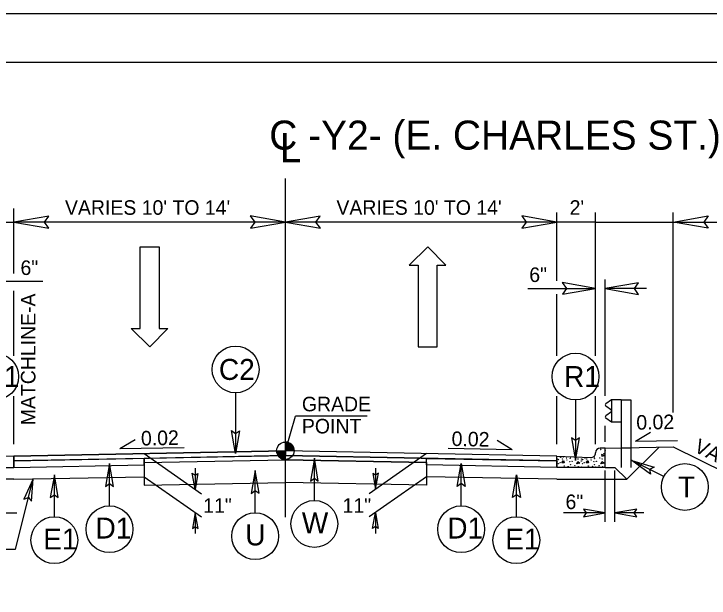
# Model space of a CAD drawing. Extents: x 1487909 to 1489267, y 497866 to 499814.
# Drawn here: x 1488985.22 to 1489021.07, y 498066.51 to 498096.65 of the extents above; entities that cross this region are included whole.
import ezdxf

# ---------------------------------------------------------------- set-up
doc = ezdxf.new("R2010")
doc.units = 0
for name, color, linetype in [('Exist XS Ground Line', 7, 'Continuous'), ('Old_Level_10', 7, 'Continuous'), ('Prop Dimension', 7, 'Continuous'), ('Prop Dimension Text', 7, 'Continuous'), ('Prop Lane Arrow CELL', 7, 'Continuous'), ('Prop Shade Light', 7, 'Continuous'), ('Prop Shade Medium', 7, 'Continuous'), ('Prop Terminator CELL', 7, 'Continuous'), ('Sheet Plot Border Outside CELL', 7, 'Continuous'), ('Sheet Typical CELL', 7, 'Continuous'), ('Typical Curb CELL', 7, 'Continuous'), ('Typical Detail Wedge2 CELL', 7, 'Continuous'), ('Typical Grade Point Symbol CELL', 7, 'Continuous'), ('Typical Guardrail CELL', 7, 'Continuous'), ('Typical Hinge Slope Arterial CELL', 7, 'Continuous'), ('Typical Hinge Slope Interstate CELL', 7, 'Continuous'), ('Typical ID Circle CELL', 7, 'Continuous'), ('Typical Pavement Slope CELL', 7, 'Continuous'), ('Typical Pavement Slope Information CELL', 7, 'Continuous'), ('Typical Terminator CELL', 7, 'Continuous'), ('Typical Text Grade Point CELL', 7, 'Continuous'), ('Typical Text ID Circle CELL', 7, 'Continuous')]:
    doc.layers.add(name, color=color, linetype=linetype)

msp = doc.modelspace()

# ---------------------------------------------------------------- linework, layer by layer
at = {"layer": 'Exist XS Ground Line'}
for p, q in [((1488991.931, 498073.498), (1488999.218, 498073.644)), ((1489006.506, 498073.498), (1488999.218, 498073.644)), ((1488991.931, 498073.498), (1488991.931, 498072.333)), ((1489006.506, 498073.498), (1489006.506, 498072.333)), ((1488991.931, 498072.333), (1488999.218, 498072.479)), ((1489006.506, 498072.333), (1488999.218, 498072.479))]:
    msp.add_line(p, q, dxfattribs=at)
at = {"layer": 'Old_Level_10'}
for p, q in [((1488991.931, 498073.718), (1488985.219, 498073.584)), ((1488985.219, 498073.584), (1488985.219, 498073.251)), ((1488991.931, 498073.385), (1488991.931, 498073.718)), ((1489006.506, 498073.385), (1489006.506, 498073.718)), ((1489006.506, 498073.718), (1489013.218, 498073.584)), ((1489013.218, 498073.584), (1489013.222, 498073.251)), ((1488985.219, 498073.251), (1488991.931, 498073.385)), ((1488991.931, 498073.385), (1488991.931, 498073.385)), ((1489013.222, 498073.251), (1489006.506, 498073.385)), ((1489006.506, 498073.385), (1489006.506, 498073.385))]:
    msp.add_line(p, q, dxfattribs=at)
at = {"layer": 'Prop Dimension'}
for p, q in [((1488999.218, 498070.68), (1488999.218, 498088.153)), ((1488985.219, 498083.267), (1488985.219, 498086.616)), ((1489013.218, 498082.873), (1489013.218, 498086.414)), ((1489015.218, 498079.005), (1489015.218, 498086.414)), ((1489019.218, 498076.089), (1489019.218, 498086.414)), ((1488983.218, 498085.915), (1488985.218, 498085.915)), ((1488999.218, 498085.914), (1488985.219, 498085.914)), ((1489013.218, 498085.914), (1488999.218, 498085.914)), ((1489015.218, 498085.914), (1489013.218, 498085.914)), ((1489015.218, 498085.914), (1489027.563, 498085.914)), ((1489015.718, 498076.954), (1489015.718, 498082.955)), ((1488986.714, 498082.846), (1488983.219, 498082.846)), ((1488985.219, 498079.005), (1488985.219, 498082.364)), ((1489011.723, 498082.484), (1489015.218, 498082.484)), ((1489013.218, 498079.005), (1489013.218, 498082.19)), ((1489017.841, 498082.484), (1489015.718, 498082.484)), ((1488985.219, 498074.455), (1488985.219, 498076.925)), ((1489013.218, 498074.455), (1489013.218, 498076.925)), ((1489015.218, 498074.455), (1489015.218, 498076.925)), ((1489015.718, 498074.565), (1489015.718, 498075.4)), ((1489015.718, 498070.445), (1489015.718, 498073.098)), ((1489016.218, 498070.445), (1489016.218, 498073.098)), ((1488985.307, 498069.033), (1488986.205, 498072.658)), ((1488982.719, 498070.904), (1488985.367, 498070.904)), ((1489015.718, 498070.904), (1489013.557, 498070.904)), ((1489017.705, 498070.904), (1489016.218, 498070.904)), ((1488979.834, 498069.033), (1488985.307, 498069.033))]:
    msp.add_line(p, q, dxfattribs=at)
at = {"layer": 'Prop Dimension Text'}
for p in [(1488999.218, 498074.114), (1489003.443, 498075.904)]:
    msp.add_line(p, (1488999.744, 498075.904), dxfattribs=at)
at = {"layer": 'Prop Lane Arrow CELL'}
for p, q in [((1488991.723, 498080.427), (1488991.723, 498084.627)), ((1488991.723, 498084.627), (1488992.713, 498084.627)), ((1488992.713, 498084.627), (1488992.713, 498080.427)), ((1489006.571, 498084.627), (1489005.611, 498083.682)), ((1489007.501, 498083.682), (1489006.571, 498084.627)), ((1489005.611, 498083.682), (1489006.061, 498083.682)), ((1489006.061, 498083.682), (1489006.061, 498079.482)), ((1489007.051, 498079.482), (1489007.051, 498083.682)), ((1489007.051, 498083.682), (1489007.501, 498083.682)), ((1488992.233, 498079.482), (1488991.273, 498080.427)), ((1488991.273, 498080.427), (1488991.723, 498080.427)), ((1488993.163, 498080.427), (1488992.233, 498079.482)), ((1488992.713, 498080.427), (1488993.163, 498080.427)), ((1489006.061, 498079.482), (1489007.051, 498079.482))]:
    msp.add_line(p, q, dxfattribs=at)
at = {"layer": 'Prop Shade Light'}
for p, q in [((1488999.218, 498074.114), (1488985.219, 498073.834)), ((1488999.218, 498073.864), (1488999.218, 498074.114)), ((1489013.218, 498073.834), (1488999.218, 498074.114)), ((1488999.218, 498074.114), (1488999.218, 498073.864)), ((1488985.219, 498073.584), (1488999.218, 498073.864)), ((1488985.219, 498073.834), (1488985.219, 498073.584)), ((1488999.218, 498073.864), (1489013.218, 498073.584)), ((1489013.218, 498073.584), (1489013.218, 498073.834))]:
    msp.add_line(p, q, dxfattribs=at)
at = {"layer": 'Prop Shade Medium'}
msp.add_lwpolyline([(1488991.931, 498073.718), (1488991.931, 498073.498), (1488999.218, 498073.644), (1489006.506, 498073.498), (1489006.506, 498073.718), (1488999.218, 498073.864)], close=True, dxfattribs=at)
at = {"layer": 'Prop Terminator CELL'}
for points in [[(1488987.018, 498086.224), (1488985.218, 498085.914), (1488987.028, 498085.594), (1488986.798, 498085.914)], [(1488997.418, 498085.604), (1488999.218, 498085.914), (1488997.408, 498086.234), (1488997.638, 498085.914)], [(1489001.018, 498086.224), (1488999.218, 498085.914), (1489001.028, 498085.594), (1489000.798, 498085.914)], [(1489011.418, 498085.604), (1489013.218, 498085.914), (1489011.408, 498086.234), (1489011.638, 498085.914)], [(1489021.018, 498085.604), (1489019.218, 498085.914), (1489021.028, 498086.234), (1489020.798, 498085.914)], [(1489013.508, 498082.19), (1489015.218, 498082.484), (1489013.499, 498082.788), (1489013.717, 498082.484)], [(1489017.428, 498082.779), (1489015.718, 498082.484), (1489017.438, 498082.18), (1489017.219, 498082.484)], [(1488986.122, 498071.519), (1488986.205, 498072.658), (1488985.739, 498071.608), (1488985.967, 498071.699)], [(1489014.593, 498070.71), (1489015.718, 498070.904), (1489014.587, 498071.104), (1489014.73, 498070.904)], [(1489017.343, 498071.098), (1489016.218, 498070.904), (1489017.349, 498070.704), (1489017.205, 498070.904)]]:
    msp.add_lwpolyline(points, close=True, dxfattribs=at)
at = {"layer": 'Sheet Plot Border Outside CELL'}
msp.add_lwpolyline([(1489051.664, 498096.654), (1488883.264, 498096.654), (1488883.264, 497986.654), (1489051.664, 497986.654)], close=True, dxfattribs=at)
at = {"layer": 'Sheet Typical CELL'}
msp.add_lwpolyline([(1489049.964, 498094.154), (1488899.964, 498094.154), (1488899.964, 497989.154), (1489049.964, 497989.154)], close=True, dxfattribs=at)
at = {"layer": 'Typical Curb CELL'}
for p, q in [((1489015.218, 498074.001), (1489015.218, 498074.011)), ((1489015.718, 498074.251), (1489015.458, 498074.251)), ((1489015.527, 498073.917), (1489015.544, 498073.827)), ((1489015.681, 498073.873), (1489015.527, 498073.917)), ((1489015.718, 498073.251), (1489015.718, 498074.251)), ((1488985.219, 498073.834), (1488983.468, 498073.761)), ((1488985.219, 498073.251), (1488985.219, 498073.834)), ((1489013.218, 498073.251), (1489013.218, 498073.834)), ((1489013.218, 498073.834), (1489014.969, 498073.761)), ((1489013.479, 498073.49), (1489013.565, 498073.61)), ((1489013.565, 498073.61), (1489013.6, 498073.497)), ((1489014.244, 498073.439), (1489014.307, 498073.554)), ((1489014.307, 498073.554), (1489014.41, 498073.479)), ((1489014.728, 498073.49), (1489014.814, 498073.61)), ((1489014.814, 498073.61), (1489014.848, 498073.497)), ((1489015.493, 498073.439), (1489015.555, 498073.554)), ((1489015.544, 498073.827), (1489015.681, 498073.873)), ((1489015.555, 498073.554), (1489015.659, 498073.479)), ((1488982.719, 498073.251), (1488985.219, 498073.251)), ((1489015.718, 498073.251), (1489013.218, 498073.251)), ((1489013.6, 498073.497), (1489013.479, 498073.49)), ((1489014.41, 498073.479), (1489014.244, 498073.439)), ((1489014.848, 498073.497), (1489014.728, 498073.49)), ((1489015.659, 498073.479), (1489015.493, 498073.439))]:
    msp.add_line(p, q, dxfattribs=at)
for centre in [(1489015.488, 498074.175), (1489015.653, 498073.958), (1489015.705, 498074.141), (1489013.235, 498073.588), (1489013.252, 498073.685), (1489013.308, 498073.651), (1489013.417, 498073.775), (1489013.513, 498073.691), (1489013.559, 498073.793), (1489013.708, 498073.73), (1489013.736, 498073.628), (1489013.885, 498073.542), (1489013.913, 498073.714), (1489013.93, 498073.764), (1489014.01, 498073.571), (1489014.187, 498073.736), (1489014.307, 498073.685), (1489014.484, 498073.588), (1489014.501, 498073.685), (1489014.557, 498073.651), (1489014.666, 498073.745), (1489014.763, 498073.691), (1489014.957, 498073.73), (1489014.985, 498073.628), (1489015.134, 498073.542), (1489015.162, 498073.714), (1489015.179, 498073.764), (1489015.259, 498073.571), (1489015.436, 498073.736), (1489015.556, 498073.685), (1489013.229, 498073.28), (1489013.292, 498073.445), (1489013.388, 498073.491), (1489013.439, 498073.257), (1489013.599, 498073.325), (1489013.805, 498073.303), (1489013.919, 498073.388), (1489013.976, 498073.274), (1489014.153, 498073.337), (1489014.324, 498073.297), (1489014.478, 498073.28), (1489014.541, 498073.445), (1489014.637, 498073.491), (1489014.688, 498073.257), (1489014.848, 498073.325), (1489015.054, 498073.303), (1489015.168, 498073.388), (1489015.225, 498073.274), (1489015.402, 498073.337), (1489015.573, 498073.297)]:
    msp.add_circle(centre, 0.00802, dxfattribs=at)
for centre, start, end in [((1489014.978, 498074.001), 267.6155, 0), ((1489015.458, 498074.011), 90, 180)]:
    msp.add_arc(centre, 0.24, start, end, dxfattribs=at)
at = {"layer": 'Typical Detail Wedge2 CELL'}
for p, q in [((1488991.931, 498073.968), (1488994.895, 498071.892)), ((1489006.506, 498073.968), (1489003.541, 498071.892)), ((1488994.564, 498073.209), (1488994.564, 498072.125)), ((1489003.873, 498073.209), (1489003.873, 498072.125)), ((1488991.931, 498072.772), (1488994.895, 498070.697)), ((1489006.506, 498072.772), (1489003.542, 498070.697)), ((1488994.575, 498070.921), (1488994.575, 498069.837)), ((1489003.862, 498070.921), (1489003.862, 498069.837))]:
    msp.add_line(p, q, dxfattribs=at)
at = {"layer": 'Typical Grade Point Symbol CELL'}
for p, q in [((1488999.218, 498074.114), (1488999.218, 498074.562)), ((1488998.771, 498074.114), (1488999.218, 498074.114)), ((1488999.217, 498073.667), (1488999.218, 498074.114)), ((1488999.218, 498074.114), (1488999.217, 498073.667)), ((1488999.666, 498074.114), (1488999.218, 498074.114))]:
    msp.add_line(p, q, dxfattribs=at)
for points in [[(1488999.222, 498074.562), (1488999.222, 498074.562), (1488999.222, 498074.114)], [(1488999.231, 498074.562), (1488999.231, 498074.114)], [(1488999.24, 498074.561), (1488999.24, 498074.114)], [(1488999.249, 498074.561), (1488999.249, 498074.114)], [(1488999.258, 498074.56), (1488999.258, 498074.114)], [(1488999.267, 498074.559), (1488999.267, 498074.114)], [(1488999.276, 498074.558), (1488999.276, 498074.114)], [(1488999.285, 498074.557), (1488999.285, 498074.114)], [(1488999.294, 498074.556), (1488999.294, 498074.114)], [(1488999.303, 498074.554), (1488999.303, 498074.114)], [(1488999.312, 498074.552), (1488999.312, 498074.114)], [(1488999.321, 498074.55), (1488999.321, 498074.114)], [(1488999.33, 498074.548), (1488999.33, 498074.114)], [(1488999.339, 498074.545), (1488999.339, 498074.114)], [(1488999.348, 498074.543), (1488999.348, 498074.114)], [(1488999.357, 498074.54), (1488999.357, 498074.114)], [(1488999.366, 498074.537), (1488999.366, 498074.114)], [(1488999.374, 498074.534), (1488999.374, 498074.114)], [(1488999.383, 498074.53), (1488999.383, 498074.114)], [(1488999.392, 498074.526), (1488999.392, 498074.114)], [(1488999.401, 498074.522), (1488999.401, 498074.114)], [(1488999.41, 498074.518), (1488999.41, 498074.114)], [(1488999.419, 498074.514), (1488999.419, 498074.114)], [(1488999.428, 498074.509), (1488999.428, 498074.114)], [(1488999.437, 498074.504), (1488999.437, 498074.114)], [(1488999.446, 498074.499), (1488999.446, 498074.114)], [(1488999.455, 498074.494), (1488999.455, 498074.114)], [(1488999.464, 498074.488), (1488999.464, 498074.114)], [(1488999.473, 498074.482), (1488999.473, 498074.114)], [(1488999.482, 498074.475), (1488999.482, 498074.114)], [(1488999.491, 498074.469), (1488999.491, 498074.114)], [(1488999.5, 498074.462), (1488999.5, 498074.114)], [(1488999.509, 498074.454), (1488999.509, 498074.114)], [(1488999.518, 498074.446), (1488999.518, 498074.114)], [(1488999.527, 498074.438), (1488999.527, 498074.114)], [(1488999.536, 498074.429), (1488999.536, 498074.114)], [(1488999.545, 498074.421), (1488999.545, 498074.114)], [(1488999.554, 498074.411), (1488999.554, 498074.114)], [(1488999.562, 498074.4), (1488999.562, 498074.114)], [(1488999.571, 498074.389), (1488999.571, 498074.114)], [(1488999.58, 498074.377), (1488999.58, 498074.114)], [(1488999.589, 498074.364), (1488999.589, 498074.114)], [(1488999.598, 498074.35), (1488999.598, 498074.114)], [(1488999.607, 498074.335), (1488999.607, 498074.114)], [(1488999.616, 498074.319), (1488999.616, 498074.114)], [(1488999.625, 498074.3), (1488999.625, 498074.114)], [(1488999.634, 498074.279), (1488999.634, 498074.114)], [(1488998.773, 498074.114), (1488998.773, 498074.065)], [(1488998.782, 498074.114), (1488998.782, 498074.013)], [(1488998.791, 498074.114), (1488998.791, 498073.981)], [(1488998.8, 498074.114), (1488998.8, 498073.954)], [(1488998.809, 498074.114), (1488998.809, 498073.933)], [(1488998.817, 498074.114), (1488998.817, 498073.914)], [(1488998.826, 498074.114), (1488998.826, 498073.897)], [(1488998.835, 498074.114), (1488998.835, 498073.881)], [(1488998.844, 498074.114), (1488998.844, 498073.868)], [(1488998.853, 498074.114), (1488998.853, 498073.855)], [(1488998.862, 498074.114), (1488998.862, 498073.843)], [(1488998.871, 498074.114), (1488998.871, 498073.832)], [(1488998.88, 498074.114), (1488998.88, 498073.821)], [(1488998.889, 498074.114), (1488998.889, 498073.811)], [(1488998.898, 498074.114), (1488998.898, 498073.801)], [(1488998.907, 498074.114), (1488998.907, 498073.792)], [(1488998.916, 498074.114), (1488998.916, 498073.784)], [(1488998.925, 498074.114), (1488998.925, 498073.776)], [(1488998.934, 498074.114), (1488998.934, 498073.768)], [(1488998.943, 498074.114), (1488998.943, 498073.761)], [(1488998.952, 498074.114), (1488998.952, 498073.754)], [(1488998.961, 498074.114), (1488998.961, 498073.748)], [(1488998.97, 498074.114), (1488998.97, 498073.742)], [(1488998.979, 498074.114), (1488998.979, 498073.736)], [(1488998.988, 498074.114), (1488998.988, 498073.73)], [(1488998.997, 498074.114), (1488998.997, 498073.725)], [(1488999.005, 498074.114), (1488999.005, 498073.72)], [(1488999.014, 498074.114), (1488999.014, 498073.715)], [(1488999.023, 498074.114), (1488999.023, 498073.711)], [(1488999.032, 498074.114), (1488999.032, 498073.707)], [(1488999.041, 498074.114), (1488999.041, 498073.703)], [(1488999.05, 498074.114), (1488999.05, 498073.699)], [(1488999.059, 498074.114), (1488999.059, 498073.695)], [(1488999.068, 498074.114), (1488999.068, 498073.692)], [(1488999.077, 498074.114), (1488999.077, 498073.689)], [(1488999.086, 498074.114), (1488999.086, 498073.686)], [(1488999.095, 498074.114), (1488999.095, 498073.684)], [(1488999.104, 498074.114), (1488999.104, 498073.682)], [(1488999.113, 498074.114), (1488999.113, 498073.68)], [(1488999.122, 498074.114), (1488999.122, 498073.678)], [(1488999.131, 498074.114), (1488999.131, 498073.676)], [(1488999.14, 498074.114), (1488999.14, 498073.674)], [(1488999.149, 498074.114), (1488999.149, 498073.673)], [(1488999.158, 498074.114), (1488999.158, 498073.671)], [(1488999.167, 498074.114), (1488999.167, 498073.67)], [(1488999.176, 498074.114), (1488999.176, 498073.669)], [(1488999.185, 498074.114), (1488999.185, 498073.668)], [(1488999.193, 498074.114), (1488999.193, 498073.668)], [(1488999.202, 498074.114), (1488999.202, 498073.667)], [(1488999.211, 498074.114), (1488999.211, 498073.667), (1488999.211, 498073.667)], [(1488999.643, 498074.254), (1488999.643, 498074.114)], [(1488999.652, 498074.224), (1488999.652, 498074.114)], [(1488999.661, 498074.178), (1488999.661, 498074.114)]]:
    msp.add_lwpolyline(points, dxfattribs=at)
msp.add_circle((1488999.218, 498074.114), 0.448, dxfattribs=at)
for start, end in [(359.9905, 89.9905), (179.9905, 269.9905)]:
    msp.add_arc((1488999.218, 498074.114), 0.448, start, end, dxfattribs=at)
at = {"layer": 'Typical Guardrail CELL'}
for p, q in [((1489016.041, 498076.743), (1489015.752, 498076.54)), ((1489016.538, 498076.743), (1489016.041, 498076.743)), ((1489016.041, 498076.743), (1489016.041, 498075.583)), ((1489016.538, 498076.743), (1489016.538, 498074.257)), ((1489016.538, 498076.743), (1489017.036, 498076.743)), ((1489017.036, 498076.743), (1489017.036, 498074.257)), ((1489016.041, 498076.21), (1489015.752, 498076.413)), ((1489016.041, 498076.116), (1489015.752, 498075.913)), ((1489016.041, 498076.163), (1489016.041, 498076.21)), ((1489016.041, 498076.163), (1489016.041, 498076.116)), ((1489016.041, 498075.583), (1489015.752, 498075.786)), ((1489016.538, 498075.583), (1489016.041, 498075.583)), ((1489016.538, 498074.257), (1489017.036, 498074.257)), ((1489016.538, 498074.257), (1489016.538, 498073.249)), ((1489017.036, 498074.257), (1489017.036, 498073.249))]:
    msp.add_line(p, q, dxfattribs=at)
for centre, start, end in [((1489015.796, 498076.476), 125.003, 235.0112), ((1489015.796, 498075.85), 125.0059, 235.0366)]:
    msp.add_arc(centre, 0.0776, start, end, dxfattribs=at)
at = {"layer": 'Typical Hinge Slope Arterial CELL'}
msp.add_line((1489019.218, 498074.321), (1489028.247, 498069.806), dxfattribs=at)
at = {"layer": 'Typical ID Circle CELL'}
for p, q in [((1488996.653, 498077.101), (1488996.653, 498073.978)), ((1489014.186, 498076.731), (1489014.186, 498073.608)), ((1489000.715, 498071.546), (1489000.715, 498073.723)), ((1489018.743, 498072.781), (1489017.085, 498073.605)), ((1488990.147, 498071.271), (1488990.147, 498073.448)), ((1489008.289, 498071.271), (1489008.289, 498073.448)), ((1488987.304, 498070.705), (1488987.304, 498072.871)), ((1488997.661, 498070.915), (1488997.661, 498073.092)), ((1489011.133, 498070.705), (1489011.133, 498072.871))]:
    msp.add_line(p, q, dxfattribs=at)
for centre in [(1488996.653, 498078.309), (1488984.251, 498077.94), (1489014.186, 498077.94), (1489019.825, 498072.243), (1489000.715, 498070.337), (1488990.147, 498070.062), (1489008.289, 498070.062), (1488987.304, 498069.496), (1488997.661, 498069.707), (1489011.133, 498069.496)]:
    msp.add_circle(centre, 1.208, dxfattribs=at)
at = {"layer": 'Typical Pavement Slope CELL'}
for p, q in [((1489015.718, 498074.251), (1489019.218, 498074.321)), ((1489018.5, 498074.306), (1489016.831, 498072.638)), ((1488985.219, 498073.834), (1488999.218, 498074.114)), ((1489013.218, 498073.834), (1488999.218, 498074.114)), ((1488985.219, 498073.584), (1488999.218, 498073.864)), ((1488991.931, 498073.498), (1488991.931, 498073.718)), ((1489013.218, 498073.584), (1488999.218, 498073.864)), ((1489006.506, 498073.498), (1489006.506, 498073.718)), ((1488985.219, 498073.251), (1488991.931, 498073.385)), ((1489013.218, 498073.251), (1489006.506, 498073.385)), ((1489015.718, 498073.251), (1489016.218, 498073.251)), ((1489016.218, 498073.251), (1489016.831, 498072.638)), ((1488985.219, 498072.638), (1488981.606, 498072.638)), ((1488985.219, 498072.638), (1488991.931, 498072.772)), ((1489013.218, 498072.638), (1489006.506, 498072.772)), ((1489013.218, 498072.638), (1489016.831, 498072.638))]:
    msp.add_line(p, q, dxfattribs=at)
at = {"layer": 'Typical Pavement Slope Information CELL'}
for p, q in [((1489017.27, 498074.605), (1489018.053, 498075.078)), ((1488990.681, 498074.221), (1488991.464, 498074.694)), ((1489010.923, 498074.161), (1489010.14, 498074.635)), ((1489017.27, 498074.605), (1489019.446, 498074.649)), ((1488990.681, 498074.221), (1488993.997, 498074.287)), ((1489010.923, 498074.161), (1489007.607, 498074.228))]:
    msp.add_line(p, q, dxfattribs=at)
at = {"layer": 'Typical Terminator CELL'}
for points in [[(1488996.855, 498075.149), (1488996.653, 498073.978), (1488996.445, 498075.156), (1488996.653, 498075.006)], [(1489013.984, 498074.78), (1489014.186, 498073.608), (1489014.394, 498074.786), (1489014.186, 498074.636)], [(1489000.917, 498072.551), (1489000.715, 498073.723), (1489000.507, 498072.545), (1489000.715, 498072.694)], [(1489018.045, 498072.902), (1489017.085, 498073.605), (1489018.233, 498073.267), (1489018.006, 498073.147)], [(1488990.349, 498072.276), (1488990.147, 498073.448), (1488989.939, 498072.27), (1488990.147, 498072.42)], [(1489008.087, 498072.276), (1489008.289, 498073.448), (1489008.497, 498072.27), (1489008.289, 498072.42)], [(1488987.505, 498071.699), (1488987.304, 498072.871), (1488987.095, 498071.692), (1488987.304, 498071.842)], [(1488994.705, 498072.945), (1488994.564, 498072.125), (1488994.418, 498072.949), (1488994.564, 498072.845)], [(1488997.863, 498071.921), (1488997.661, 498073.092), (1488997.453, 498071.914), (1488997.661, 498072.064)], [(1489003.732, 498072.945), (1489003.873, 498072.125), (1489004.019, 498072.949), (1489003.873, 498072.845)], [(1489010.931, 498071.699), (1489011.133, 498072.871), (1489011.341, 498071.692), (1489011.133, 498071.842)], [(1488994.716, 498070.101), (1488994.575, 498070.921), (1488994.429, 498070.097), (1488994.575, 498070.201)], [(1489003.721, 498070.101), (1489003.862, 498070.921), (1489004.008, 498070.097), (1489003.862, 498070.201)]]:
    msp.add_lwpolyline(points, close=True, dxfattribs=at)

# ---------------------------------------------------------------- texts
at = {"layer": 'Prop Dimension Text'}
for s, p in [("VARIES 10' TO 14'", (1488987.853, 498086.288)), ("VARIES 10' TO 14'", (1489001.853, 498086.288)), ("2'", (1489013.88, 498086.288)), ('6"', (1488985.557, 498083.182)), ('6"', (1489011.799, 498082.82)), ('6"', (1489013.667, 498071.103)), ('11"', (1488994.982, 498070.913)), ('11"', (1489002.17, 498070.913))]:
    msp.add_text(s, height=0.75, dxfattribs=at).set_placement(p)
at = {"layer": 'Typical Hinge Slope Arterial CELL'}
for s, rotation, p in [('MATCHLINE-A', 90, (1488986.33, 498075.428)), ('VAR. FILL SLOPE', 333.4658, (1489020.244, 498074.097))]:
    msp.add_text(s, height=0.75, rotation=rotation, dxfattribs=at).set_placement(p)
at = {"layer": 'Typical Hinge Slope Interstate CELL'}
for s, p in [('C -Y2- (E. CHARLES ST.)', (1488998.388, 498089.649)), ('L', (1488998.928, 498089.001))]:
    msp.add_text(s, height=1.5, dxfattribs=at).set_placement(p)
at = {"layer": 'Typical Pavement Slope Information CELL'}
for rotation, p in [(1.1457, (1489017.327, 498075.196)), (1.1457, (1488991.779, 498074.381)), (358.8543, (1489007.787, 498074.363))]:
    msp.add_text('0.02', height=0.75, rotation=rotation, dxfattribs=at).set_placement(p)
at = {"layer": 'Typical Text Grade Point CELL'}
for s, p in [('GRADE', (1489000.072, 498076.148)), ('POINT', (1489000.072, 498075.007))]:
    msp.add_text(s, height=0.75, dxfattribs=at).set_placement(p)
at = {"layer": 'Typical Text ID Circle CELL'}
for s, height, p in [('C2', 1.0817, (1488995.792, 498077.768)), ('R1', 1.0817, (1488983.657, 498077.399)), ('R1', 1.0817, (1489013.593, 498077.399)), ('T', 1.082, (1489019.469, 498071.702)), ('W', 1.082, (1489000.067, 498069.859)), ('D1', 1.0817, (1488989.427, 498069.584)), ('D1', 1.0817, (1489007.569, 498069.584)), ('E1', 1.0817, (1488986.73, 498069.018)), ('U', 1.082, (1488997.151, 498069.228)), ('E1', 1.0817, (1489010.559, 498069.018))]:
    msp.add_text(s, height=height, dxfattribs=at).set_placement(p)

doc.saveas('drawing.dxf')
